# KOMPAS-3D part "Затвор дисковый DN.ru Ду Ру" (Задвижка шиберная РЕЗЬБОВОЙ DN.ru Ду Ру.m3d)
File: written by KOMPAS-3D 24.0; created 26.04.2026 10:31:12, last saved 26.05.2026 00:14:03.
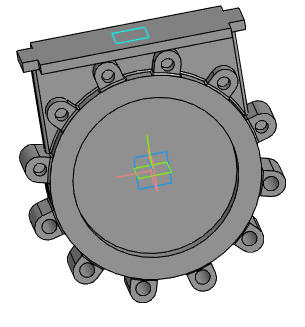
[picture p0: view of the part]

Document properties: Автор: R2D2; Полное имя файла: E:\Работа\Зайцев\GVKR1331M-1W-Fb-2P Задвижка шиберная с выдвижным штоком DN.ru Ду50-300 Ру16-10-6 с пневмоприводом\исходные материалы\DN250\Задвижка шиберная РЕЗЬБОВОЙ DN.ru Ду Ру.m3d

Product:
- Part/product: Затвор дисковый DN.ru Ду Ру
    Масса: 18.2
    Раздел спецификации: Прочие изделия
    Примечание: D050-23732

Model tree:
1. Смещенная плоскость:2
2. Диск
3. Корпус
4. Элемент выдавливания:3
     Расстояние 1 = 30
5. Элемент вращения:1
     Угол 1 = 360
6. Корпус штока
7. Элемент выдавливания:6  (with: Грань.Элемент вращения:1)
     Расстояние 1 = 215
8. Ушко  (with: Ребро.Элемент вращения:1)
9. Элемент выдавливания:5
10. Эскиз:1  (with: Ребро.Элемент выдавливания:5)
11. Элемент выдавливания:12
     Расстояние 1 = 35
12. Элемент выдавливания:13
13. Массив по концентрической сетке:2  (with: Элемент выдавливания:13, Эскиз:1, Элемент выдавливания:12, Элемент выдавливания:5, Грань.Элемент вращения:1)  (12 pattern instances)
     Шаг 2 = 360
14. Эскиз:2  (labels: Ребро.Элемент выдавливания:5.Экземпляр ( 1, 11 ))
15. Элемент выдавливания:14
16. площадка  (with: Грань.Элемент выдавливания:6, Ребро.Элемент выдавливания:5)
17. Элемент выдавливания:15
     Расстояние 2 = 15
18. Скругление:10  (with: Ребро.Элемент выдавливания:6)
     Радиус = 5
19. Эскиз:4  (labels: Задвижка шиберная с выдвижным штоком DN.ru Ду50 Ру16; Затвор дисковый DN.ru Ду200 Ру16)
20. Элемент выдавливания:16  (with: Грань.Элемент вращения:1)
     Расстояние 1 = 160.5; Смещение 1 = 1
21. Эскиз:5  (labels: Задвижка шиберная DN.ru Ду50 Ру10; Затвор дисковый DN.ru Ду200 Ру16)
22. Скругление:14  (with: Ребро.Элемент выдавливания:16)
     Радиус = 3
23. Элемент выдавливания:17  (with: Грань.Элемент вращения:1)
     Расстояние 1 = 160.484; Смещение 1 = 1

Expressions: c-8-2*t; v1301/2; dd/2; 360/n*2+360/n; d/2+40
Referenced files in E:\Работа\Зайцев\GVKR1331E-1W-Fb-2P Задвижка шиберная DN.ru Ду50-300 Ру16-10-6\исходные материалы\DN50\: GVKR1331E-1W-Fb-2P Задвижка шиберная с выдвижным штоком DN.ru Ду50 Ру16.a3d, GVKR1331E-1W-Fb-2P Задвижка шиберная DN.ru Ду50 Ру16.a3d
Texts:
  Угловой размер с обрывом
  GOST 26.020 Pr3
  var3D
  ширина затвора по металлу
  площадка под крепеж
  DN+10
  dk+20
  dk-10
  Плоскость ZY.Начало координат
